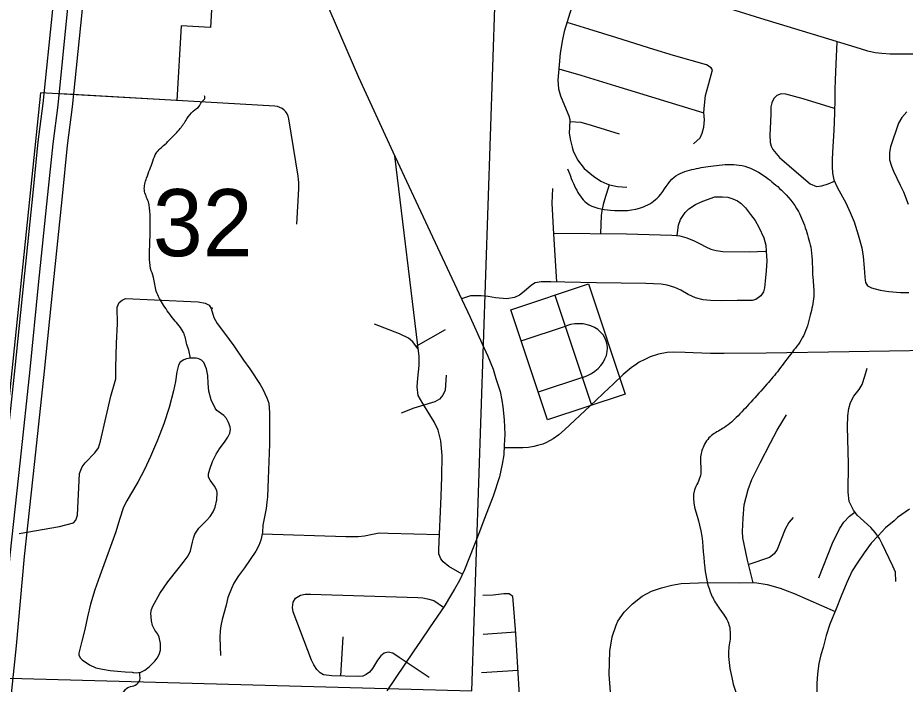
# Model space of a CAD drawing. Extents: x 1219626 to 1426462, y 456797 to 752399.
# Drawn here: x 1317947 to 1323903, y 627040 to 631511 of the extents above; entities that cross this region are included whole.
import ezdxf

# ---------------------------------------------------------------- set-up
doc = ezdxf.new("R2010")
doc.units = 0
for name, color, linetype in [('Cities Incorporated Area', 7, 'Continuous'), ('Culture', 7, 'Continuous'), ('Lakes and Ponds', 7, 'Continuous'), ('Local Roads Improved', 7, 'Continuous'), ('Local Roads Paved', 7, 'Continuous'), ('Masks', 7, 'Continuous'), ('Narrow River Creek and Branch and Slough', 7, 'Continuous'), ('Section Lines', 7, 'Continuous'), ('Section Numbers', 7, 'Continuous'), ('State Route Divided Highway Outline and Fill', 7, 'Continuous'), ('State Routes Highway Center Lines', 7, 'Continuous')]:
    doc.layers.add(name, color=color, linetype=linetype)

msp = doc.modelspace()

# ---------------------------------------------------------------- linework, layer by layer
at = {"layer": 'Cities Incorporated Area'}
for p, q in [((1319278.5, 632110.7), (1319240.3, 631446.1)), ((1319044, 631457.4), (1319015.2, 630955.7)), ((1319240.3, 631446.1), (1319044, 631457.4)), ((1318100.7, 631008.3), (1317262.3, 622926.7)), ((1319015.2, 630955.7), (1318100.7, 631008.3))]:
    msp.add_line(p, q, dxfattribs=at)
at = {"layer": 'Culture'}
for p, q in [((1321551, 629651.3), (1321797.1, 628911.6)), ((1321325.2, 629344), (1321629.1, 629445.1)), ((1321744, 629099.8), (1321440, 628998.7))]:
    msp.add_line(p, q, dxfattribs=at)
msp.add_lwpolyline([(1321777, 629726.5), (1322023.1, 628986.8), (1321501.7, 628813.3), (1321255.6, 629553)], close=True, dxfattribs=at)
msp.add_ellipse((1321686.6, 629272.5), major_axis=(-210.2, -69.9), ratio=0.821498, start_param=1.570796, end_param=4.712389, dxfattribs=at)
at = {"layer": 'Lakes and Ponds'}
msp.add_lwpolyline([(1318714.5, 627121.6), (1318721.6, 627119.2), (1318741.7, 627117.9), (1318772.2, 627122.1), (1318800, 627135.6), (1318829.3, 627157.2), (1318867.9, 627194), (1318883.7, 627215.4), (1318896.5, 627239.4), (1318905, 627268.3), (1318905.8, 627313.5), (1318896.5, 627356.2), (1318886.8, 627375.8), (1318866.4, 627403.9), (1318851, 627433.4), (1318844.1, 627465.4), (1318841, 627516.2), (1318844.7, 627540.9), (1318853, 627564.1), (1318900.1, 627648.2), (1318954, 627728.4), (1319023.2, 627814.3), (1319058.3, 627856.6), (1319090.6, 627900.7), (1319106.3, 627935.3), (1319119.1, 627992.5), (1319125.9, 628020.8), (1319136.1, 628047.2), (1319163, 628086.2), (1319213.7, 628138.8), (1319238.3, 628166.6), (1319258.9, 628197.7), (1319272.2, 628228.7), (1319283.6, 628277.5), (1319286.6, 628324.4), (1319283.6, 628340.4), (1319268.2, 628368.1), (1319238.2, 628409.4), (1319228.5, 628430.2), (1319227.2, 628451.2), (1319236, 628484.1), (1319255.3, 628534.2), (1319278.7, 628583.8), (1319300.9, 628620.6), (1319339.1, 628672), (1319356.3, 628697.8), (1319369.8, 628724.4), (1319374, 628748.2), (1319371.9, 628767.4), (1319362.5, 628796.5), (1319348, 628823.4), (1319330.5, 628842.5), (1319299, 628865.3), (1319284.4, 628877.6), (1319272.8, 628892.7), (1319246.1, 628947.6), (1319229.2, 629005.6), (1319225.6, 629058), (1319223.2, 629110.5), (1319213.2, 629155.2), (1319195.5, 629197.7), (1319181.3, 629213.9), (1319163, 629223.3), (1319143.9, 629228), (1319107.1, 629228.7), (1319079.7, 629223.3), (1319061, 629216.1), (1319038.2, 629200.6), (1319025.2, 629179.8), (1319015.5, 629137.1), (1319006.2, 629071.9), (1318993.6, 629007.6), (1318962.8, 628897.2), (1318928.2, 628787.8), (1318886, 628676.9), (1318839.1, 628568), (1318797.5, 628481.3), (1318754, 628395.7), (1318704, 628312.4), (1318679, 628270.8), (1318657.6, 628227.3), (1318630.5, 628145.8), (1318605.3, 628063.5), (1318551.4, 627915.9), (1318497.8, 627768.1), (1318464.7, 627673.6), (1318435.2, 627578), (1318415.4, 627493), (1318397.6, 627407.7), (1318376.6, 627328.3), (1318358, 627249.3), (1318358, 627236.8), (1318367.2, 627216.7), (1318379.7, 627203.1), (1318429.2, 627170.1), (1318472.1, 627151.1), (1318516.4, 627140.4), (1318566.8, 627132.9), (1318617.4, 627128.5), (1318668.5, 627124), (1318714.5, 627121.6)], dxfattribs=at)
at = {"layer": 'Local Roads Improved'}
for p, q in [((1319673.5, 630917.9), (1318238.3, 631000.4)), ((1319829, 630448.7), (1319766.5, 630834.1)), ((1319820.7, 630127.1), (1319833.6, 630362.8)), ((1319249.4, 629566.7), (1319252.2, 629559.4))]:
    msp.add_line(p, q, dxfattribs=at)
for centre, radius, start, end in [((1319667.8, 630818.1), 100, 9.21944, 86.71062), ((1319434.2, 630384.6), 400, 356.87941, 9.21944)]:
    msp.add_arc(centre, radius, start, end, dxfattribs=at)
at = {"layer": 'Local Roads Paved'}
for p, q in [((1320620.1, 629308.9), (1320817, 629419.2)), ((1321289, 627389.3), (1321070.1, 627374.9)), ((1320128.7, 627357.6), (1320113.2, 627095.6)), ((1321304.6, 627132.4), (1321060, 627116.2))]:
    msp.add_line(p, q, dxfattribs=at)
for points in [[(1319843.3, 632019.7), (1320233.9, 631113.7), (1320465, 630611.4), (1320586.8, 630347.4), (1320700, 630109.6), (1320908.8, 629660), (1320982.3, 629503.3), (1321062.5, 629329.3), (1321101.2, 629240.3), (1321138, 629154.3), (1321155.4, 629092.4), (1321174.7, 629031.5), (1321185.3, 629004.4), (1321196.5, 628945.4), (1321202.7, 628901.5), (1321211.4, 628813.5), (1321215.3, 628714.8), (1321212.4, 628644.3), (1321208.5, 628579.5), (1321197.9, 628517.6), (1321180.5, 628432.5), (1321138, 628302.9), (1321079.9, 628151.1), (1321041.3, 628050.6), (1320944.6, 627807.9), (1320910.7, 627735.4), (1320877.9, 627677.4), (1320838.2, 627611.6), (1320813.1, 627569.1), (1320710.6, 627418.2), (1320655.5, 627337), (1320600.4, 627257.7), (1320424.4, 626996.7)], [(1324010.1, 631267), (1323857.4, 631267), (1323801.3, 631267), (1323747.1, 631270.8), (1323700.7, 631275.7), (1323652.4, 631288.2), (1323603.1, 631301.8), (1323389.4, 631366.6), (1322934.9, 631506.8), (1322588.8, 631613.1)], [(1321664.4, 631577.8), (1321615.1, 631418.3), (1321602.6, 631366.1), (1321588.1, 631273.3), (1321580.3, 631194.9), (1321570.7, 631093.4), (1321575.5, 631034.4), (1321589, 630988), (1321626.7, 630895.2), (1321645.6, 630854.1), (1321652.4, 630828.5), (1321650.4, 630771.9), (1321648.5, 630738.6), (1321654.3, 630697), (1321666.9, 630644.3), (1321673.6, 630618.2), (1321704.1, 630557.7), (1321749.5, 630501.2), (1321810, 630448.5), (1321860.2, 630415.6), (1321900.8, 630397.7), (1321918.3, 630390.5), (1321972.9, 630379.4), (1322035.7, 630375)], [(1322482, 630666), (1322526.4, 630706.7), (1322540, 630736.6), (1322551.6, 630778.2), (1322556.4, 630825.6), (1322550.6, 630874.9), (1322556.4, 630924.2), (1322562.2, 630990.9), (1322584.4, 631070.2), (1322609.6, 631161.1), (1322601.8, 631175.6), (1322569, 631194.9), (1322348.5, 631258.8), (1322215.1, 631299.4), (1321966.6, 631377.7), (1321780, 631434.7), (1321634, 631479.3)], [(1323443.4, 631350.2), (1323436.3, 631199.8), (1323433.4, 631095.3), (1323429.5, 631027.7), (1323430.5, 630953.2), (1323427.6, 630882.6), (1323425.6, 630804.3), (1323420.8, 630716.3), (1323416.9, 630646.7), (1323413.1, 630563.6), (1323413.1, 630511.3), (1323414, 630468.8), (1323424.7, 630423.4), (1323447.9, 630370.2), (1323504, 630270.6), (1323533.9, 630204.8), (1323560, 630142.9), (1323588.1, 630054), (1323611.3, 629967.9), (1323620, 629909.9), (1323627.7, 629833.5), (1323631.6, 629771.7), (1323636.4, 629734.9), (1323649, 629712.7), (1323676.1, 629699.1), (1323734.1, 629683.7), (1323794, 629675), (1323871.4, 629669.2), (1323926.5, 629668.2)], [(1321577.8, 631168.8), (1321726.8, 631127.3), (1321957.9, 631055.7), (1322550.9, 630872.6)], [(1323428.4, 630903.2), (1323218.7, 630966.7), (1323158.8, 630984.2), (1323101.7, 630997.7), (1323070.8, 631000.6), (1323041.8, 630990.9), (1323020.5, 630970.6), (1323007, 630940.6), (1323000.2, 630914.5), (1323001.2, 630869.1), (1322999.2, 630814), (1322994.4, 630727), (1322997.3, 630674.7), (1323003.1, 630649.6), (1323014.7, 630627.4), (1323059.2, 630573.2), (1323188.8, 630462), (1323264.2, 630397.2), (1323306.7, 630378.9), (1323342.5, 630382.7), (1323385, 630397.2), (1323428.3, 630415)], [(1323913, 630881.2), (1323880.1, 630842.5), (1323858.8, 630804.8), (1323804.7, 630646.2), (1323796.9, 630608.5), (1323797.9, 630559.2), (1323811.4, 630515.7), (1323825, 630481.8), (1323869.5, 630389), (1323891.7, 630342.6), (1323923.6, 630260.4)], [(1321985, 630730.8), (1321797.4, 630788.8), (1321727.8, 630808.2), (1321651.8, 630812.7)], [(1320930.6, 627778), (1320841.1, 627829.2), (1320801.5, 627861.1), (1320786, 627882.3), (1320773.4, 627914.2), (1320773.4, 627943.3), (1320788.9, 628302.9), (1320793.7, 628430.6), (1320794.7, 628574.6), (1320787, 628672.3), (1320767.6, 628744.8), (1320741.5, 628799.9), (1320665.1, 628922.7), (1320634.2, 628976.9), (1320628.4, 629035.8), (1320631.3, 629093.9), (1320641, 629178), (1320641.9, 629239.9), (1320477.2, 630584.9)], [(1321535.4, 630365.3), (1321531.5, 630266.7), (1321543.1, 630058.8), (1321562.7, 629738.8)], [(1321916.9, 630391), (1321883.9, 630289), (1321875.7, 630259), (1321867.5, 630216.4), (1321863.6, 630185.5), (1321858.1, 630063.2)], [(1322372.4, 630050.9), (1322382.4, 630120.7), (1322394.9, 630157.5), (1322425.4, 630203.9), (1322451, 630229), (1322496.5, 630259.5), (1322545.8, 630281.2), (1322625.1, 630310.2), (1322677.7, 630310.7), (1322712.6, 630307.3), (1322746.4, 630295.7), (1322776.4, 630283.6), (1322802, 630265.7), (1322832, 630235.8), (1322865.3, 630191.8), (1322896.8, 630150.2), (1322920.9, 630105.7), (1322954.3, 630034.7), (1322966.9, 629984.9), (1322969.8, 629944.7), (1322974.1, 629881.4), (1322969.8, 629812.8), (1322962, 629745.1), (1322957.7, 629699.1), (1322952.3, 629673), (1322933.5, 629646), (1322900.1, 629621.3), (1322875.5, 629614.5), (1322774.4, 629613.6), (1322669.5, 629612.6), (1322595.6, 629613.6), (1322547.2, 629619.9), (1322495, 629633.4), (1322447.1, 629655.1), (1322396.4, 629684.6), (1322357.2, 629702.5), (1322306, 629717), (1322265.4, 629723.8), (1322214.6, 629727.2), (1322162.9, 629728.6), (1321830.7, 629732), (1321618.5, 629737.3), (1321524.7, 629739.8), (1321460.9, 629738.8), (1321420.3, 629734), (1321394.2, 629717.5), (1321346.3, 629675.9), (1321313.9, 629651.3), (1321281.1, 629634.4), (1321229.3, 629625.7), (1321152.5, 629632.4), (1321104.6, 629640.6), (1321058.2, 629646.9), (1321024.8, 629646.9), (1321000.7, 629646.9), (1320984.7, 629646.9), (1320925.1, 629625.3)], [(1321542.7, 630066.6), (1322031.9, 630061.2), (1322336, 630053), (1322367.9, 630051.6), (1322391.1, 630048.2), (1322438.4, 630035.6), (1322487.3, 630015.3), (1322526.4, 629995), (1322565.1, 629974.2), (1322598.9, 629959.2), (1322633.3, 629950.5), (1322679.2, 629942.8), (1322859, 629941.4), (1322964.9, 629945.7)], [(1317956.9, 628051.1), (1318227.6, 628098.4), (1318320.4, 628122.6), (1318336.9, 628140), (1318349.4, 628174.8), (1318362, 628453.3), (1318380.4, 628499.7), (1318398.7, 628525.8), (1318464.5, 628591.6), (1318489.6, 628625.4), (1318503.2, 628671.8), (1318539.9, 628837.2), (1318572.8, 628973.5), (1318605.7, 629089.5), (1318606.6, 629164), (1318610.5, 629329.3), (1318616.3, 629457.9), (1318614.4, 629569.1), (1318627.9, 629602), (1318648.2, 629617.4), (1318671.4, 629628.1), (1318865.7, 629619.4), (1319158.7, 629605.8), (1319204.2, 629597.1), (1319231.2, 629582.6), (1319244.8, 629560.4), (1319263.1, 629499.5), (1319285.4, 629460.8), (1319334.7, 629396), (1319397.5, 629310), (1319463.3, 629213.3), (1319503.9, 629156.2), (1319574.5, 629050.8), (1319592.9, 629019.9), (1319619, 628961.9), (1319632.5, 628925.1), (1319636.4, 628861.3), (1319636.4, 628818.8), (1319636.4, 628650.5), (1319627.7, 628417.5), (1319622.8, 628296.7), (1319619, 628262.8), (1319614.1, 628220.3), (1319592.9, 628108.1), (1319589, 628057.8), (1319579.3, 628007.6), (1319565.8, 627970.8), (1319544.5, 627933.1), (1319468.1, 627820.9), (1319428.5, 627766.8), (1319397.5, 627717.5), (1319381.1, 627681.7), (1319357.9, 627621.8), (1319346.3, 627571.5), (1319318.3, 627473.8), (1319309.6, 627433.2), (1319304.7, 627398.4), (1319302.8, 627354.9), (1319307.6, 627233.1)], [(1320636.3, 629286), (1320599.4, 629338), (1320569.4, 629361.2), (1320508.5, 629390.2), (1320342.2, 629455)], [(1324067.7, 629278.5), (1323526.7, 629270.3), (1322969.8, 629261.1), (1322687.9, 629258.2), (1322596, 629259.2), (1322480.5, 629263.6), (1322426.8, 629266), (1322349, 629266.9), (1322306, 629266), (1322247.5, 629253.9), (1322192.4, 629236.5), (1322154.7, 629219.1), (1322117.4, 629200.2), (1322099.5, 629188.1), (1322064.7, 629164), (1322011.1, 629117.1), (1321940, 629051.8), (1321917.3, 629028.1), (1321789.2, 628907.7), (1321616.6, 628746.7), (1321579.4, 628713.4), (1321540.7, 628685.8), (1321496.7, 628661.7), (1321471.5, 628651.5), (1321436.3, 628641.4), (1321409.7, 628634.1), (1321374.4, 628628.3), (1321337.6, 628626.4), (1321211.3, 628625.8)], [(1320821.8, 629113.2), (1320816, 629013.6), (1320800.5, 628978.8), (1320778.3, 628951.7), (1320747.3, 628934.3), (1320605.2, 628891.8), (1320521.1, 628857.9)], [(1323840.4, 627730.5), (1323836.6, 627792.4), (1323820.1, 627833), (1323747.6, 627981.9), (1323729.3, 628018.7), (1323701.2, 628059.3), (1323672.2, 628091.2), (1323581.3, 628174.3), (1323556.2, 628207.2), (1323540.7, 628240.1), (1323527.2, 628267.2), (1323520.4, 628329), (1323521.4, 628519.5), (1323516.5, 628766.1), (1323517.5, 628840.5), (1323525.2, 628890.8), (1323534.9, 628929.5), (1323558.1, 628973), (1323594.9, 629017.5), (1323613.2, 629050.4), (1323632.6, 629107.4), (1323648, 629160.6)], [(1322883.2, 627721.7), (1322845.5, 627872.7), (1322812.6, 628021.6), (1322811.7, 628066), (1322814.6, 628154), (1322822.3, 628244.9), (1322848.4, 628346.5), (1322873.5, 628413.2), (1322928.7, 628525.3), (1322998.3, 628660.7), (1323043.7, 628744.8), (1323106.6, 628847.3)], [(1323151, 628159.8), (1323121.1, 628125), (1323097.9, 628081.5), (1323042.8, 627944.2), (1323024.4, 627914.2), (1322991.5, 627890.1), (1322852.5, 627844.5)], [(1323931.3, 628214), (1323852, 628157.9), (1323828.8, 628137.6), (1323770.8, 628090.2), (1323721.5, 628037), (1323675.1, 627986.8), (1323626.8, 627921), (1323579.4, 627852.4), (1323546.5, 627800.2), (1323510.7, 627721.8), (1323474, 627630.9), (1323439.2, 627545.9), (1323397.6, 627443.4), (1323372.5, 627367.9), (1323351.2, 627287.7), (1323337.7, 627238.4), (1323324.1, 627178.4), (1323314.5, 627110.8), (1323310.6, 627046), (1323310.6, 626973.5)], [(1323324.1, 627753.7), (1323416, 627986.8), (1323461.4, 628083.5), (1323490.4, 628127), (1323528.1, 628168.5), (1323565.6, 628195)], [(1320777.7, 628042.9), (1320432.1, 628051.1), (1320372.2, 628053), (1320327.7, 628045.3), (1320273.6, 628032.7), (1320231, 628029.8), (1320147.9, 628028.8), (1319587.1, 628047.9)], [(1321925, 626989.9), (1321917.3, 627105), (1321920.2, 627262.6), (1321936.6, 627359.2), (1321962.7, 627436.6), (1321974.3, 627463.7), (1322015.9, 627523.6), (1322073, 627579.7), (1322136.8, 627630.9), (1322199.6, 627664.8), (1322266.3, 627688), (1322336, 627705.4), (1322399.8, 627717), (1322572.8, 627722.8), (1322787.5, 627720.9), (1322892.9, 627721.8), (1322977, 627708.3), (1323064, 627684.1), (1323156.8, 627648.3), (1323432.2, 627528.6)], [(1320708.7, 627084.6), (1320507.5, 627220), (1320465, 627248.1), (1320434.1, 627254.8), (1320407, 627249), (1320382.8, 627231.6), (1320360.6, 627200.7), (1320328.7, 627146.5), (1320308.4, 627121.4), (1320285.2, 627105), (1320262, 627094.3), (1320232, 627092.4), (1320055, 627097.2), (1319999, 627103), (1319977.7, 627116.6), (1319955.4, 627139.8), (1319934.2, 627169.7), (1319919.7, 627201.6), (1319794.9, 627525.6), (1319790.1, 627555.5), (1319794.9, 627590.3), (1319811.4, 627617.4), (1319844.3, 627637.7), (1319876.2, 627643.5), (1319911.9, 627644.5), (1320633.2, 627622.2), (1320666.1, 627620.3), (1320698, 627613.5), (1320739.6, 627601), (1320804.7, 627556.8)], [(1321398.7, 625530.6), (1321390.3, 625742.6), (1321383.6, 625878), (1321360.3, 626194.1), (1321349.7, 626347.9), (1321335.2, 626623.4), (1321316.8, 626929.9), (1321289.8, 627378.6), (1321275.3, 627577.8), (1321269.5, 627629), (1321245.3, 627646.4), (1321209.5, 627646.4), (1321137, 627638.7), (1321068.3, 627635.8)]]:
    msp.add_lwpolyline(points, dxfattribs=at)
at = {"layer": 'Masks'}
msp.add_line((1319032.5, 630976.8), (1319032.5, 630976.8), dxfattribs=at)
at = {"layer": 'Narrow River Creek and Branch and Slough'}
for points in [[(1321728.4, 635030.7), (1321684.8, 634960.7), (1321658.1, 634922.6), (1321646.7, 634888.3), (1321620, 634850.1), (1321597.1, 634815.8), (1321562.9, 634770.1), (1321524.8, 634716.8), (1321505.7, 634644.4), (1321490.5, 634579.6), (1321490.5, 634518.6), (1321498.1, 634461.4), (1321501.9, 634404.3), (1321501.9, 634377.6), (1321486.7, 634328.1), (1321490.5, 634270.9), (1321521, 634206.1), (1321559.1, 634148.9), (1321623.8, 634084.2), (1321730.5, 633977.5), (1321764.7, 633935.5), (1321840.9, 633897.4), (1321901.9, 633863.1), (1321970.4, 633832.6), (1322023.7, 633794.5), (1322099.9, 633714.5), (1322164.7, 633638.3), (1322202.7, 633569.7), (1322248.4, 633504.9), (1322290.3, 633447.7), (1322377.9, 633360.1), (1322412.2, 633333.4), (1322499.8, 633318.2), (1322648.4, 633302.9), (1322747.4, 633287.7), (1322823.6, 633264.8), (1322859.4, 633230.3), (1322878.4, 633157.9), (1322927.9, 633081.6), (1322988.9, 633013), (1323042.2, 632921.6), (1323076.5, 632830.1), (1323137.4, 632704.4), (1323183.1, 632582.4), (1323217.4, 632506.2), (1323266.9, 632433.8), (1323331.7, 632361.4), (1323430.7, 632258.5), (1323529.7, 632182.3), (1323609.7, 632136.5), (1323682.1, 632079.4), (1323731.6, 632048.9), (1323781.1, 631972.7), (1323845.9, 631926.9), (1323963.9, 631888.8), (1324059.1, 631869.8), (1324146.7, 631869.8), (1324222.9, 631862.2), (1324360, 631820.2), (1324459.1, 631782.1), (1324569.5, 631766.9), (1324699, 631766.9), (1324870.4, 631759.3), (1325007.5, 631759.3), (1325133.2, 631751.6), (1325228.4, 631717.3), (1325297, 631667.8), (1325392.2, 631618.3), (1325457, 631587.8), (1325529.3, 631584), (1325571.2, 631568.7), (1325712.9, 631518.2), (1325754.8, 631480.1), (1325895.7, 631331.4), (1325960.5, 631262.8), (1326086.2, 631156.1), (1326185.2, 631041.8), (1326257.6, 630946.5), (1326299.5, 630855.1), (1326322.3, 630729.3), (1326288, 630653.1), (1326238.5, 630580.7), (1326173.8, 630504.5), (1326128.1, 630451.1), (1326116.7, 630386.4), (1326116.7, 630310.1), (1326150.9, 630253), (1326208.1, 630176.8), (1326234.7, 630134.8), (1326250, 630066.2), (1326280.4, 630009.1)], [(1319104.7, 629228.2), (1319097.9, 629269.8), (1319082.7, 629319.3), (1319059.8, 629399.4), (1318995.1, 629487), (1318926.5, 629582.3), (1318877, 629677.6), (1318858, 629769), (1318838.9, 629830), (1318831.3, 629910), (1318835.1, 630039.6), (1318835.1, 630192), (1318823.7, 630275.9), (1318797, 630355.9), (1318812.3, 630435.9), (1318854.2, 630550.2), (1318877, 630603.6), (1318934.1, 630660.8), (1318976, 630702.7), (1319037, 630767.5), (1319082.7, 630832.3), (1319124.6, 630885.6), (1319166.5, 630919.9), (1319189.3, 630954.2), (1319200.8, 630965.6), (1319200.8, 630988.5)], [(1321637.6, 630498.4), (1321691, 630368), (1321764.5, 630268.8), (1321926.1, 630221.1), (1322146.5, 630243.1), (1322249.3, 630312.9), (1322351.8, 630441.3), (1322471.7, 630492.7), (1322597.4, 630515.6), (1322751.7, 630527), (1322826, 630515.6), (1322968.8, 630441.3), (1323071.6, 630355.5), (1323185.9, 630212.6), (1323237.3, 630086.9), (1323271.6, 629955.4), (1323283, 629766.8), (1323288.7, 629641), (1323265.9, 629515.2), (1323220.2, 629378.1), (1323145.9, 629269.4), (1323054.5, 629149.4), (1322974.5, 629052.2), (1322865.9, 628932.2), (1322768.8, 628829.3), (1322677.4, 628755), (1322603.1, 628709.2), (1322546, 628629.2), (1322528.9, 628543.5), (1322528.9, 628440.6), (1322488.9, 628343.4), (1322523.2, 628106.5), (1322557.4, 627820.7), (1322603.1, 627637.7), (1322648.8, 627557.7), (1322711.7, 627460.5), (1322728.8, 627369.1), (1322717.4, 627266.2), (1322734.5, 627106.1), (1322786, 626940.4), (1322877.4, 626808.9), (1322945.9, 626643.1), (1322963.1, 626303.2), (1322934.5, 626171.7), (1322871.7, 626034.5), (1322803.1, 625925.9), (1322717.4, 625851.6), (1322614.6, 625794.4), (1322557.4, 625760.2), (1322511.7, 625731.6), (1322477.5, 625657.3), (1322488.9, 625537.2), (1322488.9, 625462.9), (1322477.5, 625422.9), (1322460.3, 625348.6), (1322431.7, 625217.1), (1322414.6, 625079.9), (1322420.3, 624908.4), (1322420.3, 624822.7), (1322380.3, 624708.4), (1322363.2, 624645.5), (1322306.1, 624514), (1322283.2, 624422.5), (1322283.2, 624336.8), (1322294.6, 624245.3), (1322288.9, 624136.7), (1322288.9, 624096.7), (1322243.2, 623976.7), (1322191.8, 623890.9), (1322163.2, 623805.2), (1322151.8, 623719.4), (1322140.4, 623656.6), (1322146.4, 623604.6)], [(1318456.4, 626266.9), (1318466.9, 626315.3), (1318474.5, 626386.5), (1318497.4, 626465.2), (1318520.3, 626521.1), (1318558.3, 626559.2), (1318581.2, 626615.1), (1318576.1, 626681.2), (1318548.2, 626752.3), (1318555.8, 626808.2), (1318593.9, 626881.9), (1318637.1, 626950.5), (1318665, 626998.7), (1318692.9, 627021.6), (1318736.1, 627034.3), (1318766.6, 627069.9), (1318766.6, 627105.4), (1318766.5, 627121.3)]]:
    msp.add_spline(points, degree=3, dxfattribs=at)
at = {"layer": 'Section Lines'}
for p, q in [((1320995.4, 626995.9), (1321172.4, 632281.9)), ((1315676.4, 627142.4), (1320995.4, 626995.9))]:
    msp.add_line(p, q, dxfattribs=at)
at = {"layer": 'State Route Divided Highway Outline and Fill'}
for points in [[(1317298.7, 621166.5), (1317424.8, 622369.6), (1317560.7, 623586.5), (1317684.9, 624815.2), (1317819.8, 626114.6), (1317876, 626699.5), (1317939.1, 627297.5), (1317993.5, 627897), (1318062.3, 628533.6), (1318127.3, 629141.4), (1318184.6, 629710.1), (1318246.7, 630315.5), (1318281.4, 630654.6), (1318315.4, 630912.8), (1318378.7, 631546.2), (1318435.9, 632143.7), (1318495.8, 632726.5), (1318563.9, 633201.1), (1318598.8, 633360.1), (1318635.4, 633610.6), (1318695.6, 633843.9), (1318722.5, 633932.4), (1318883.7, 634518.6)], [(1318530.4, 633988), (1318503, 633898), (1318439, 633650.1), (1318401.9, 633396), (1318367, 633236.8), (1318297.3, 632750.9), (1318236.9, 632163.5), (1318179.6, 631565.7), (1318116.7, 630935.8), (1318082.8, 630677.9), (1318047.7, 630335.9), (1317985.6, 629730.4), (1317928.4, 629162), (1317863.4, 628555), (1317794.4, 627916.7), (1317740.1, 627317), (1317677.1, 626719.6), (1317620.8, 626134.5), (1317485.9, 624835.6), (1317361.8, 623607.6), (1317226, 622391.1), (1317099.8, 621188)]]:
    msp.add_lwpolyline(points, dxfattribs=at)
at = {"layer": 'State Routes Highway Center Lines'}
msp.add_lwpolyline([(1318626.5, 633960.2), (1318599.3, 633871), (1318537.2, 633630.3), (1318500.3, 633378.1), (1318465.4, 633218.9), (1318396.5, 632738.7), (1318336.4, 632153.6), (1318279.1, 631556), (1318216.1, 630924.3), (1318182.1, 630666.2), (1318147.2, 630325.7), (1318085.1, 629720.2), (1318027.8, 629151.7), (1317962.8, 628544.3), (1317893.9, 627906.9), (1317839.6, 627307.2), (1317776.5, 626709.6), (1317720.3, 626124.5), (1317585.4, 624825.4), (1317461.2, 623597), (1317325.4, 622380.3), (1317199.3, 621177.2)], dxfattribs=at)

# ---------------------------------------------------------------- texts
at = {"layer": 'Section Numbers'}
msp.add_text('32', height=450, rotation=359.9999, dxfattribs=at).set_placement((1318854.1, 629911.8))

doc.saveas('drawing.dxf')
